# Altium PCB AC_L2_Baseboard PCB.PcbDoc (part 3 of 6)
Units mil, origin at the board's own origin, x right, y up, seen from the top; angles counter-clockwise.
Board outline 7290 x 7055 mil, 4 copper layers (Top Layer, Layer 1, Layer 2, Bottom Layer), stack 70.356 mil thick; 510 components, 285 nets, 1364 pads, 522 vias.
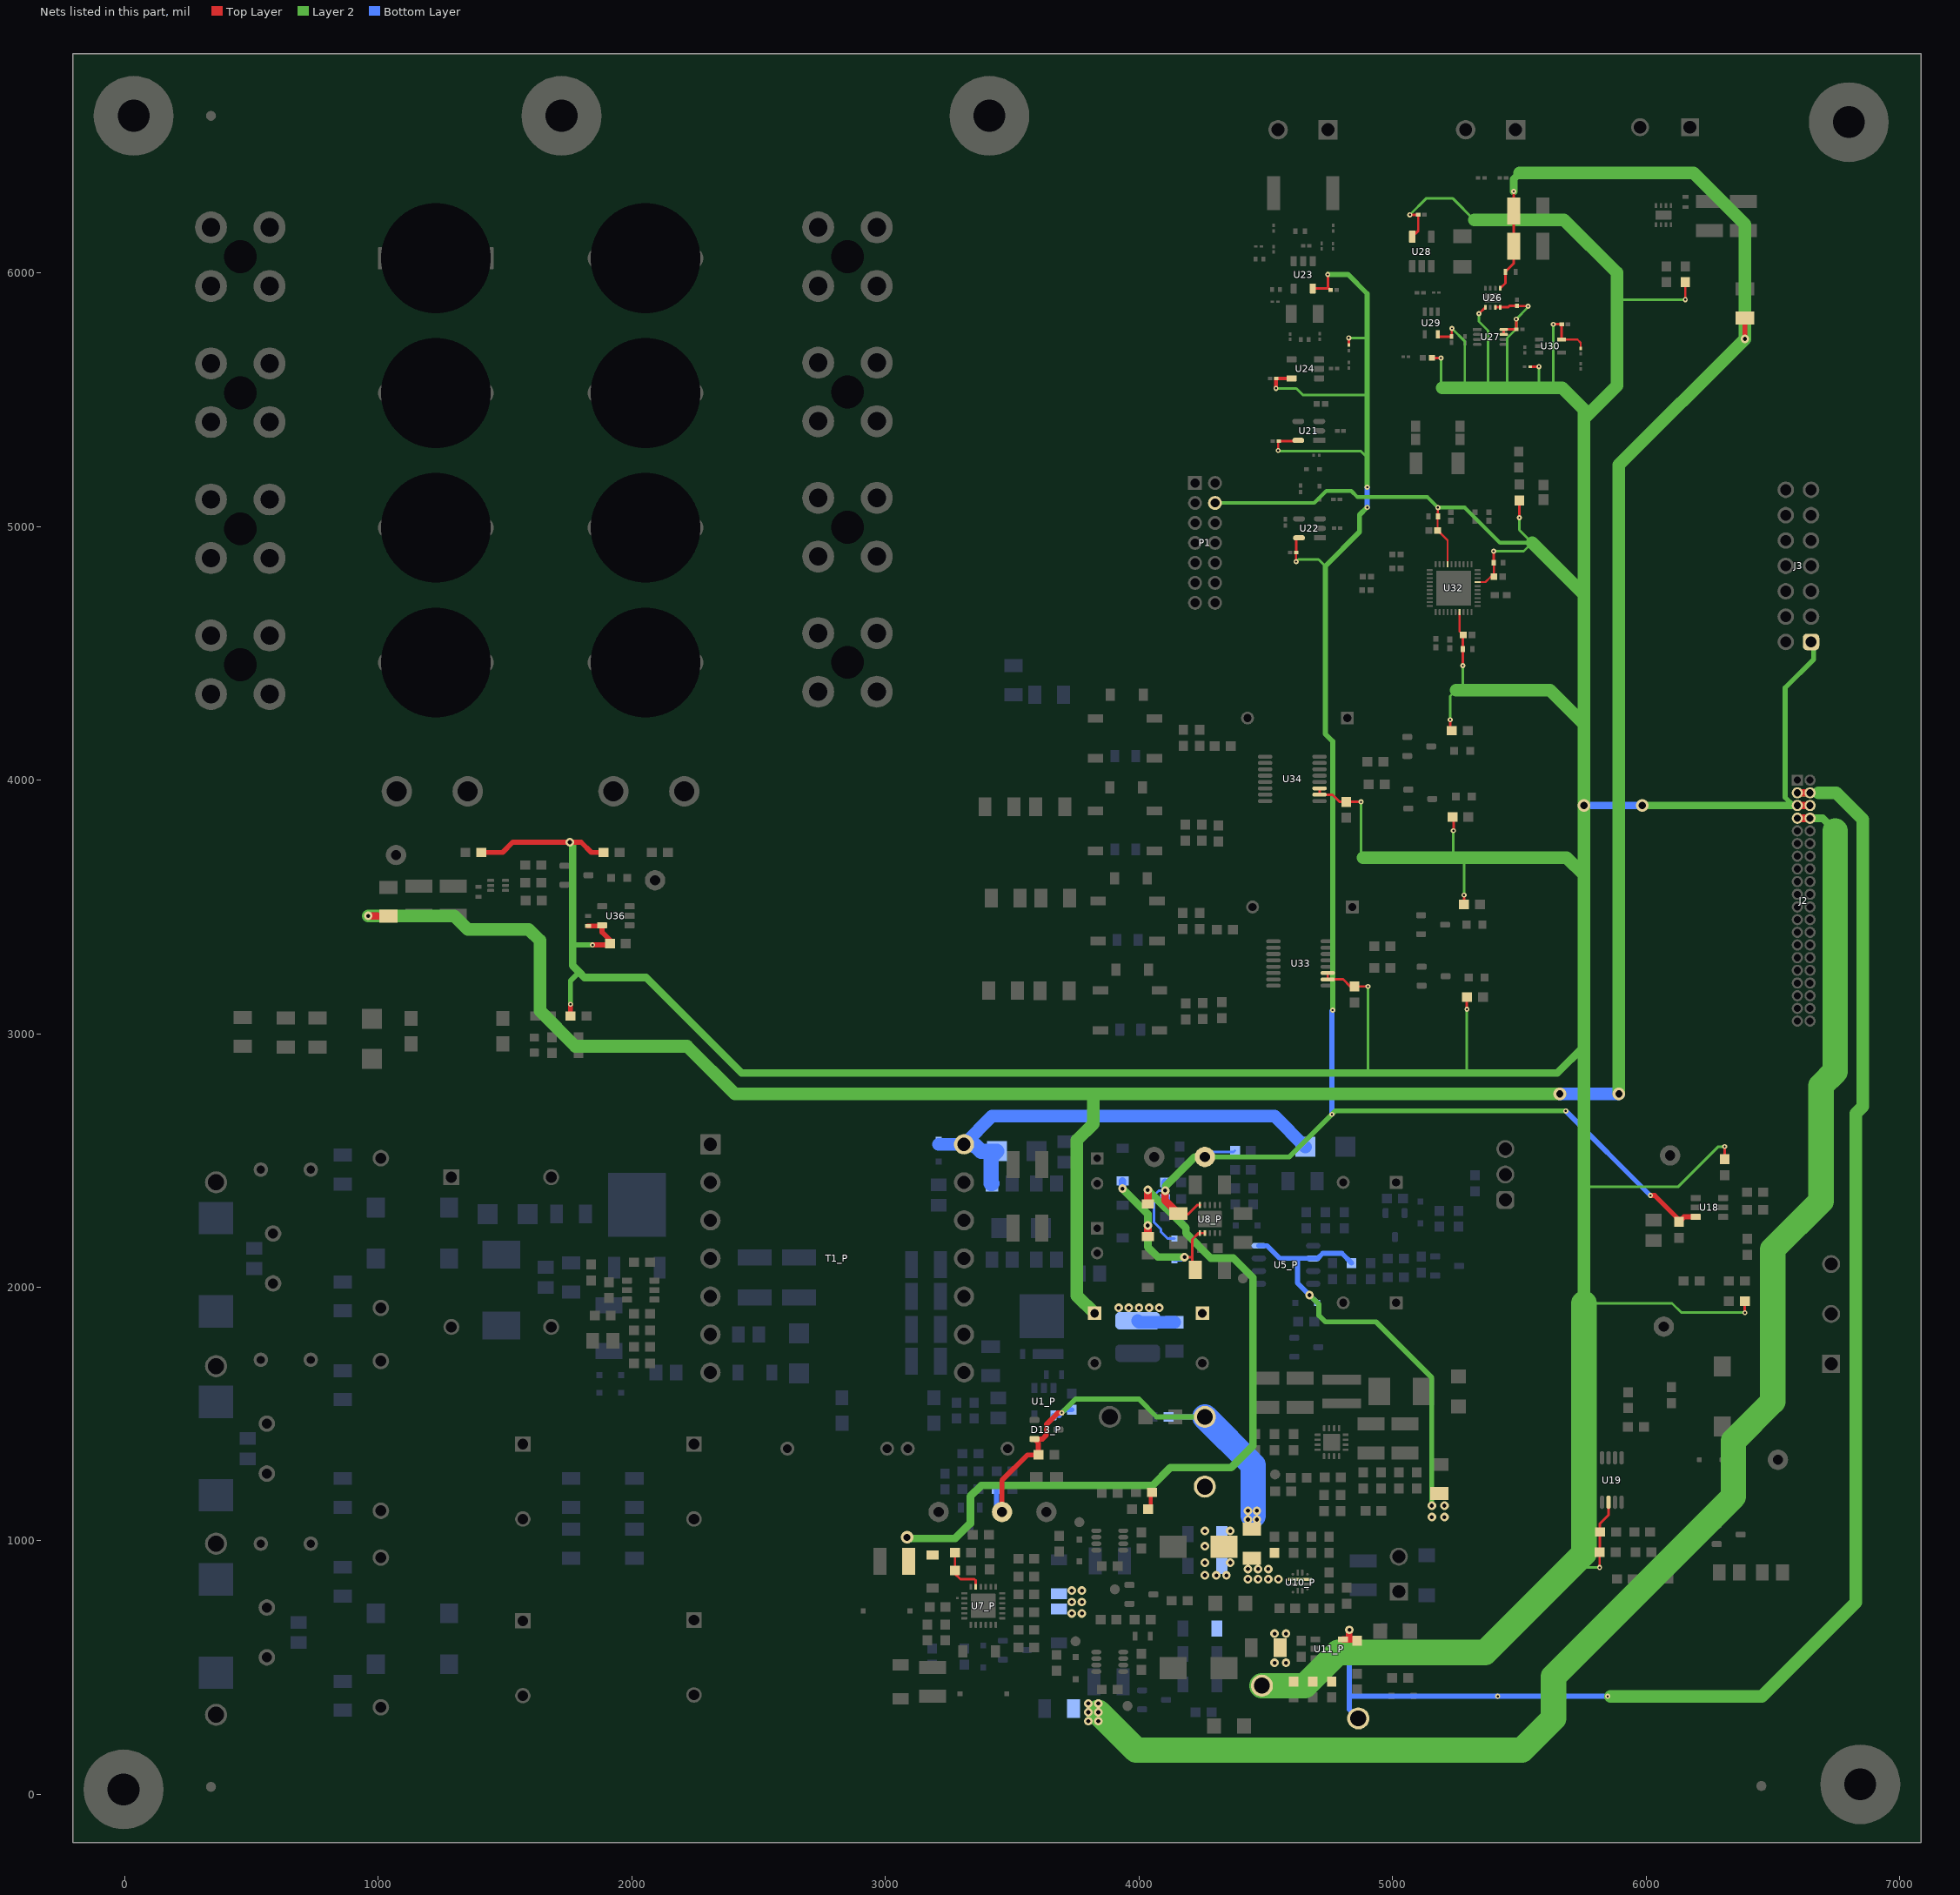
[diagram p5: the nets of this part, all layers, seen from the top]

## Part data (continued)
J16 J17: library part CMP-1502-03324-1, "Series 1377 - 5.00 mm Horizontal Entry with Pressure Clamp WR-TBL, 2 pin", Manufacturer="Wurth Elektronik", Operating Temperature=-30to120degC
J19 J20 J21 J22 J23 J24 J25 J26: library part CMP-0078526-1, "Power Element Bush, M3, TH", Current_A=50A, Manufacturer="Wurth Elektronik", Supplier Part Number 1=732-10882-1-ND
K1: library part CMP-0094655-1, "Power Her 40A 4NO 1NC 12VDC", Coil Current_A=333mA, Coil Power_W=490mW, Coil Resistance=36O, Coil Voltage_VDC=12V, Contact Rating_A=40A, Manufacturer=Panasonic, Operating Temperature Range=to, Switching Power=30W
L1_P L3_P: library part CMP-0003090-1, "Ferrite Bead, 1000 ohm @ 100 MHz, 0.2 A, 0805", Manufacturer="Wurth Elektronik", Supplier Part Number 1=732-1606-1-ND, Value1="0.45 ohm", Value2=0.2A, ValueDisplayed="1000 ohm"
L2_P L4_P L6_P: library part CMP-0064523-2, "Inductor, Wirewound, Ferrite, 150 uH, 2 A, 0.16 ohm, TH", Manufacturer="Wurth Elektronik", Value1="0.16 ohm", Value2=2A, ValueDisplayed=150uH
L5_P: library part CMP-0013107-2, "Coupled inductor, 6.8 mH, 1 A, 0.3 ohm, TH", Manufacturer="Wurth Elektronik", ValueDisplayed=6.8mH
L7_P: library part CMP-0064228-1
L8_P L10_P: library part CMP-0063804-1, "Inductor, Shielded Drum Core, Ferrite, 10 uH, 1 A, 0.12 ohm, SMD", Manufacturer="Wurth Elektronik", Supplier Part Number 1=732-1025-1-ND, Value1="0.12 ohm", Value2=1A, ValueDisplayed=10uH
L9_P L12_P L14_P: library part CMP-0003140-1, "Ferrite Bead, 280 ohm @ 100 MHz, 3.5 A, 1206", Manufacturer="Wurth Elektronik", Supplier Part Number 1=732-6132-1-ND, Value1="0.022 ohm", Value2=3.5A, ValueDisplayed="280 ohm"
L11_P L16_P: library part CMP-0086103-1, "Ferrite Bead, 600 ohm @ 100 MHz, 2.5 A, 1206", Manufacturer=Wuerth, Value1="0.038 ohm", Value2=2.5A, ValueDisplayed="600 ohm"
L13_P L17_P: library part CMP-0063928-1, "Inductor, Shielded Drum Core, Superflux, 4.7 uH, 6 A, 0.02 ohm, SMD", Manufacturer="Wurth Elektronik", Supplier Part Number 1=732-1153-1-ND, Value1="0.02 ohm", Value2=6A, ValueDisplayed=4.7uH
L15_P: library part CMP-0061090-1, "Inductor, Shielded, 3.3 uH, 5 A, 0.0286 ohm, SMD", Manufacturer=Coilcraft, Value1="0.0286 ohm", Value2=5A, ValueDisplayed=3.3uH
L18: library part CMP-0064815-2, "Inductor, Shielded Drum Core, Metal Composite, 220 uH, 0.44 A, 0.92 ohm, SMD", Manufacturer="Wurth Elektronik", Supplier Part Number 1=732-4045-1-ND, Value1="0.92 ohm", Value2=0.44A, ValueDisplayed=220uH
LBL1: library part CMP-0003625-1, "Thermal Transfer Printable Labels, 0.650\" W x 0.200\" H - 10,000 per roll", Manufacturer=Brady, Supplier Part Number 1=97C5133
LOGO1 LOGO5: library part CMP-0074835-1, "IEC 61010-1 High Voltage Warning"
Logo2: library part CMP-0074844-1
Logo3: library part CMP-0074847-1, "FCC_disclaimer"
Logo4: library part CMP-0074769-1
NT1_P NT2_P NT3: library part CMP-0078142-2, "Single point connection between nets.", Manufacturer=N/A
P1: library part CMP-2000-05240-1, "Header, Pitch 2 mm, 2 x 7 Position, Height 6.4 mm, Tail Length 2.5 mm, -55 to 105 degC, RoHS, Tube", Current Rating=2A, Manufacturer=Molex, Voltage Rating=125V
Q1_P: library part CMP-0089849-1, "Mosfet, N-Ch, 200V, 24A, 150Deg C Rohs Compliant: Yes", Digikey Part Number=BSC500N20NS3GATMA1CT-ND, Drain To Source Breakdown Voltage=200V, Input Capacitace At Vds="2770pF @ 100V", Manufacturer=Infineon, Operating Temperature Range="-55°C to +175°C", Pulse Drain Current=97A, Typ Forward Diode Voltage=1V
Q2_P: library part CMP-0091039-1, "Trans MOSFET N-CH 600V 4A 3-Pin(2+Tab) DPAK T/R", Digikey Part Number=IPD95R2K0P7ATMA1CT-ND, Drain To Source Breakdown Voltage=950V, Input Capacitace At Vds="330pF @ 400V", Manufacturer="Infineon Technologies", Mouser Part Number=726-IPD95R2K0P7ATMA1, Operating Temperature Range="-55°C to +150°C", Power_W=37W, Pulse Drain Current=10A, Typ Forward Diode Voltage=0.9V
Q3_P: library part CMP-0001232-1, "MOSFET, N-CH, 60 V, 14 A, TO-220FP", Alternate Manufacturer=None, Manufacturer=Vishay, Value2="24 nC"
Q4_P: library part CMP-0000419-2, "Transistor, NPN, 40 V, 0.2 A, SOT-23", Manufacturer="ON Semiconductor", Supplier Part Number 1=MMBT3904LT1GOSCT-ND, Value1="0.2 A", Value2=300
Q5_P Q6_P Q7_P Q8_P Q9: library part CMP-0000755-1, "MOSFET, N-CH, 50 V, 0.22 A, SOT-23", Alternate Manufacturer=None, Manufacturer="Fairchild Semiconductor", Supplier Part Number 1=BSS138CT-ND, Value2="1.7 nC"
Q10 Q11 Q12 Q13 Q14: library part CMP-0000377-2, "Transistor, NPN, 30 V, 0.1 A, SOT-23", Manufacturer="ON Semiconductor", Supplier Part Number 1=BC848CLT1GOSCT-ND, Value1="0.1 A", Value2=800
R1_P R6_P: library part CMP-0020619-3, "RES, 1.0 k, 5%, 0.125 W, AEC-Q200 Grade 0, 0805", Manufacturer=Panasonic, Power_W=125mW, Supplier Part Number 1=P1.0KACT-ND, TempCo="200 ppm/C", Tolerance_%=5%, Value2=0.125W, Value_Code=1k00, ValueDisplayed=1.0k
R2_P R4_P R7_P R9_P R12_P R16_P R19_P: library part CMP-0018684-3, "RES, 470 k, 5%, 0.25 W, AEC-Q200 Grade 0, 1206", Manufacturer=Vishay-Dale, Power_W=250mW, Supplier Part Number 1=541-470KECT-ND, TempCo="200 ppm/C", Tolerance_%=5%, Value2=0.25W, Value_Code=470k
R3_P R10_P R15_P: library part CMP-0020842-3, "RES, 10.0 k, 1%, 0.125 W, AEC-Q200 Grade 0, 0805", Manufacturer=Vishay-Dale, Power_W=125mW, Supplier Part Number 1=541-10.0KCCT-ND, TempCo="100 ppm/C", Tolerance_%=1%, Value2=0.125W, Value_Code=10k0, ValueDisplayed=10.0k
R5_P R8_P R13_P R17_P: library part CMP-0018610-3, "RES, 1.0 M, 5%, 0.25 W, AEC-Q200 Grade 0, 1206", Manufacturer=Vishay-Dale, Power_W=250mW, Supplier Part Number 1=541-1.0MECT-ND, TempCo="200 ppm/C", Tolerance_%=5%, Value2=0.25W, Value_Code=1M00, ValueDisplayed=1.0M
R11_P: library part CMP-0018578-3, "RES, 10, 5%, 0.25 W, AEC-Q200 Grade 0, 1206", Manufacturer=Vishay-Dale, Power_W=250mW, Supplier Part Number 1=541-10ECT-ND, TempCo="200 ppm/C", Tolerance_%=5%, Value2=0.25W, Value_Code=10R0, ValueDisplayed=10
R14_P R200_P: library part CMP-0018759-2, "RES, 0, 5%, 0.25 W, 1206", Manufacturer="Yageo America", Power_W=250mW, Supplier Part Number 1=311-0.0ERCT-ND, TempCo="200 ppm/C", Tolerance_%=5%, Value2=0.25W, Value_Code=0000, ValueDisplayed=0
R20_P R36_P R40_P R45_P R58_P R64_P R68_P R79_P: library part CMP-0023153-5, "RES, 4.70 k, 1%, 0.1 W, 0603", Manufacturer=Yageo, Power_W=100mW, Supplier Part Number 1=311-4.70KHRCT-ND, TempCo="100 ppm/C", Tolerance_%=1%, Value2=0.1W, Value_Code=4k70, ValueDisplayed=4.70k
R21_P: library part CMP-0022448-4, "RES, 49.9, 1%, 0.1 W, AEC-Q200 Grade 0, 0603", Manufacturer=Vishay-Dale, Power_W=100mW, Supplier Part Number 1=541-49.9HCT-ND, TempCo="100 ppm/C", Tolerance_%=1%, Value2=0.1W, Value_Code=49R9, ValueDisplayed=49.9
R22_P: library part CMP-0018603-3, "RES, 1.0 k, 5%, 0.25 W, AEC-Q200 Grade 0, 1206", Manufacturer=Vishay-Dale, Power_W=250mW, Supplier Part Number 1=541-1.0KECT-ND, TempCo="200 ppm/C", Tolerance_%=5%, Value2=0.25W, Value_Code=1k00, ValueDisplayed=1.0k
R23_P: library part CMP-0020497-3, "RES, 20, 5%, 0.125 W, AEC-Q200 Grade 0, 0805", Manufacturer=Vishay-Dale, Power_W=125mW, Supplier Part Number 1=541-20ACT-ND, TempCo="200 ppm/C", Tolerance_%=5%, Value2=0.125W, Value_Code=20R0, ValueDisplayed=20
R24_P: library part CMP-0022277-4, "RES, 2.49 k, 1%, 0.1 W, AEC-Q200 Grade 0, 0603", Manufacturer=Vishay-Dale, Power_W=100mW, Supplier Part Number 1=541-2.49KHCT-ND, TempCo="100 ppm/C", Tolerance_%=1%, Value2=0.1W, Value_Code=2k49, ValueDisplayed=2.49k
R25_P: library part CMP-0023252-5, "RES, 6.81 k, 1%, 0.1 W, 0603", Manufacturer=Yageo, Power_W=100mW, Supplier Part Number 1=311-6.81KHRCT-ND, TempCo="100 ppm/C", Tolerance_%=1%, Value2=0.1W, Value_Code=6k81, ValueDisplayed=6.81k
R26_P R28_P: library part CMP-0021759-3, "RES, 60.4 k, 1%, 0.125 W, AEC-Q200 Grade 0, 0805", Manufacturer=Panasonic, Power_W=125mW, Supplier Part Number 1=P60.4KCCT-ND, TempCo="100 ppm/C", Tolerance_%=1%, Value2=0.125W, Value_Code=60k4, ValueDisplayed=60.4k
R27_P: library part CMP-0023066-5, "RES, 38.3 k, 1%, 0.1 W, 0603", Manufacturer=Yageo, Power_W=100mW, Supplier Part Number 1=311-38.3KHRCT-ND, TempCo="100 ppm/C", Tolerance_%=1%, Value2=0.1W, Value_Code=38k3, ValueDisplayed=38.3k
R29 R83: library part CMP-0018664-3, "RES, 390 k, 5%, 0.25 W, AEC-Q200 Grade 0, 1206", Manufacturer=Vishay-Dale, Power_W=250mW, Supplier Part Number 1=541-390KECT-ND, TempCo="200 ppm/C", Tolerance_%=5%, Value2=0.25W, Value_Code=390k
R29_P R32_P R34_P R39_P R41_P R49_P R53_P R55_P R65_P R70_P R77_P R80_P: library part CMP-0022746-5, "RES, 10.0 k, 1%, 0.1 W, 0603", Manufacturer=Yageo, Power_W=100mW, Supplier Part Number 1=311-10.0KHRCT-ND, TempCo="100 ppm/C", Tolerance_%=1%, Value2=0.1W, Value_Code=10k0, ValueDisplayed=10.0k
R30_P R54_P R57_P R61_P R74_P: library part CMP-0021990-4, "RES, 100 k, 1%, 0.1 W, AEC-Q200 Grade 0, 0603", Manufacturer=Vishay-Dale, Power_W=100mW, Supplier Part Number 1=541-100KHCT-ND, TempCo="100 ppm/C", Tolerance_%=1%, Value2=0.1W, Value_Code=100k
R31_P R62_P: library part CMP-0023036-5, "RES, 33.2 k, 1%, 0.1 W, 0603", Manufacturer=Yageo, Power_W=100mW, Supplier Part Number 1=311-33.2KHRCT-ND, TempCo="100 ppm/C", Tolerance_%=1%, Value2=0.1W, Value_Code=33k2, ValueDisplayed=33.2k
R33_P R43_P R44_P: library part CMP-0022109-5, "RES, 1.00 k, 1%, 0.1 W, AEC-Q200 Grade 0, 0603", Manufacturer=Vishay-Dale, Power_W=100mW, Supplier Part Number 1=541-1.00KHCT-ND, TempCo="100 ppm/C", Tolerance_%=1%, Value2=0.1W, Value_Code=1k00, ValueDisplayed=1.00k
R35_P: library part CMP-0016530-2, "RES, 0.5, 1%, 1 W, 2010", Manufacturer="Stackpole Electronics Inc", Power_W=1W, Supplier Part Number 1=CSRN2010FKR500CT-ND, TempCo="250 ppm/C", Tolerance_%=1%, Value_Code=R500, ValueDisplayed=0.5
R37_P: library part CMP-0023037-5, "RES, 33.0 k, 1%, 0.1 W, 0603", Manufacturer=Yageo, Power_W=100mW, Supplier Part Number 1=311-33.0KHRCT-ND, TempCo="100 ppm/C", Tolerance_%=1%, Value2=0.1W, Value_Code=33k0, ValueDisplayed=33.0k
R38_P: library part CMP-0022478-4, "RES, 4.99, 1%, 0.1 W, AEC-Q200 Grade 0, 0603", Manufacturer=Vishay-Dale, Power_W=100mW, Supplier Part Number 1=541-4.99HHCT-ND, TempCo="100 ppm/C", Tolerance_%=1%, Value2=0.1W, Value_Code=4R99, ValueDisplayed=4.99
R42_P: library part CMP-0022762-5, "RES, 11.8 k, 1%, 0.1 W, 0603", Manufacturer=Yageo, Power_W=100mW, Supplier Part Number 1=311-11.8KHRCT-ND, TempCo="100 ppm/C", Tolerance_%=1%, Value2=0.1W, Value_Code=11k8, ValueDisplayed=11.8k
R46_P: library part CMP-0023318-5, "RES, 91.0 k, 1%, 0.1 W, 0603", Manufacturer=Yageo, Power_W=100mW, Supplier Part Number 1=311-91.0KHRCT-ND, TempCo="100 ppm/C", Tolerance_%=1%, Value2=0.1W, Value_Code=91k0, ValueDisplayed=91.0k
R47_P: library part CMP-0022661-3, "RES, 976 k, 1%, 0.1 W, AEC-Q200 Grade 0, 0603", Manufacturer=Vishay-Dale, Power_W=100mW, Supplier Part Number 1=541-976KHCT-ND, TempCo="100 ppm/C", Tolerance_%=1%, Value2=0.1W, Value_Code=976k
R48_P: library part CMP-0022655-4, "RES, 93.1 k, 1%, 0.1 W, AEC-Q200 Grade 0, 0603", Manufacturer=Vishay-Dale, Power_W=100mW, Supplier Part Number 1=541-93.1KHCT-ND, TempCo="100 ppm/C", Tolerance_%=1%, Value2=0.1W, Value_Code=93k1, ValueDisplayed=93.1k
R50_P: library part CMP-0023239-5, "RES, 68.0 k, 1%, 0.1 W, 0603", Manufacturer=Yageo, Power_W=100mW, Supplier Part Number 1=311-68.0KHRCT-ND, TempCo="100 ppm/C", Tolerance_%=1%, Value2=0.1W, Value_Code=68k0, ValueDisplayed=68.0k
R51_P: library part CMP-0023273-4, "RES, 787 k, 1%, 0.1 W, 0603", Manufacturer=Yageo, Power_W=100mW, Supplier Part Number 1=311-787KHRCT-ND, TempCo="100 ppm/C", Tolerance_%=1%, Value2=0.1W, Value_Code=787k
R52_P R69_P: library part CMP-0021991-4, "RES, 100, 1%, 0.1 W, AEC-Q200 Grade 0, 0603", Manufacturer=Vishay-Dale, Power_W=100mW, Supplier Part Number 1=541-100HCT-ND, TempCo="100 ppm/C", Tolerance_%=1%, Value2=0.1W, Value_Code=100R, ValueDisplayed=100
R56_P: library part CMP-0020835-3, "RES, 100, 1%, 0.125 W, AEC-Q200 Grade 0, 0805", Manufacturer=Vishay-Dale, Power_W=125mW, Supplier Part Number 1=541-100CCT-ND, TempCo="100 ppm/C", Tolerance_%=1%, Value2=0.125W, Value_Code=100R, ValueDisplayed=100
R60_P: library part CMP-0022436-4, "RES, 475 k, 1%, 0.1 W, AEC-Q200 Grade 0, 0603", Manufacturer=Vishay-Dale, Power_W=100mW, Supplier Part Number 1=541-475KHCT-ND, TempCo="100 ppm/C", Tolerance_%=1%, Value2=0.1W, Value_Code=475k
R63_P: library part CMP-0023342-3, "RES, 11.0 k, 1%, 0.1 W, AEC-Q200 Grade 0, 0603", Manufacturer="Stackpole Electronics Inc", Power_W=100mW, Supplier Part Number 1=RMCF0603FT11K0CT-ND, TempCo="100 ppm/C", Tolerance_%=1%, Value2=0.1W, Value_Code=11k0, ValueDisplayed=11.0k
R66_P: library part CMP-0022588-5, "RES, 750, 1%, 0.1 W, AEC-Q200 Grade 0, 0603", Manufacturer=Vishay-Dale, Power_W=100mW, Supplier Part Number 1=541-750HCT-ND, TempCo="100 ppm/C", Tolerance_%=1%, Value2=0.1W, Value_Code=750R, ValueDisplayed=750
R67_P R75_P R191: library part CMP-0023133-5, "RES, 47.0 k, 1%, 0.1 W, 0603", Manufacturer=Yageo, Power_W=100mW, Supplier Part Number 1=311-47.0KHRCT-ND, TempCo="100 ppm/C", Tolerance_%=1%, Value2=0.1W, Value_Code=47k0, ValueDisplayed=47.0k
R71_P: library part CMP-0022735-5, "RES, 100 k, 1%, 0.1 W, 0603", Manufacturer=Yageo, Power_W=100mW, Supplier Part Number 1=311-100KHRCT-ND, TempCo="100 ppm/C", Tolerance_%=1%, Value2=0.1W, Value_Code=100k
R72_P: library part CMP-0023162-4, "RES, 510 k, 1%, 0.1 W, 0603", Manufacturer=Yageo, Power_W=100mW, Supplier Part Number 1=311-510KHRCT-ND, TempCo="100 ppm/C", Tolerance_%=1%, Value2=0.1W, Value_Code=510k
R76_P: library part CMP-0023180-5, "RES, 54.9 k, 1%, 0.1 W, 0603", Manufacturer=Yageo, Power_W=100mW, Supplier Part Number 1=311-54.9KHRCT-ND, TempCo="100 ppm/C", Tolerance_%=1%, Value2=0.1W, Value_Code=54k9, ValueDisplayed=54.9k
R78_P: library part CMP-0025309-3, "RES, 46.4 k, 0.5%, 0.1 W, 0603", Manufacturer="Yageo America", Power_W=100mW, TempCo="50 ppm/C", Tolerance_%=0.5%, Value2=0.1W, Value_Code=46k4, ValueDisplayed=46.4k
R82: library part CMP-0025700-2, "RES, 100, 5%, 0.1 W, 0603", Manufacturer=Vishay-Dale, Power_W=100mW, Supplier Part Number 1=541-100GCT-ND, TempCo="200 ppm/C", Tolerance_%=5%, Value2=0.1W, Value_Code=100R, ValueDisplayed=100
R84: library part CMP-0025917-5, "RES, 39 k, 5%, 0.1 W, 0603", Manufacturer=Yageo, Power_W=100mW, Supplier Part Number 1=311-39KGRCT-ND, TempCo="100 ppm/C", Tolerance_%=5%, Value2=0.1W, Value_Code=39k0, ValueDisplayed=39k
R85: library part CMP-0025756-4, "RES, 220, 5%, 0.1 W, AEC-Q200 Grade 0, 0603", Manufacturer=Vishay-Dale, Power_W=100mW, Supplier Part Number 1=541-220GCT-ND, TempCo="200 ppm/C", Tolerance_%=5%, Value2=0.1W, Value_Code=220R, ValueDisplayed=220
R86 R88 R89 R94 R96: library part CMP-0022901-4, "RES, 200 k, 1%, 0.1 W, 0603", Manufacturer=Yageo, Power_W=100mW, Supplier Part Number 1=311-200KHRCT-ND, TempCo="100 ppm/C", Tolerance_%=1%, Value2=0.1W, Value_Code=200k
R87: library part CMP-0025899-5, "RES, 1.0 k, 5%, 0.1 W, 0603", Manufacturer=Yageo, Power_W=100mW, Supplier Part Number 1=311-1.0KGRCT-ND, TempCo="100 ppm/C", Tolerance_%=5%, Value2=0.1W, Value_Code=1k00, ValueDisplayed=1.0k
R90: library part CMP-0025931-5, "RES, 56 k, 5%, 0.1 W, 0603", Manufacturer=Yageo, Power_W=100mW, Supplier Part Number 1=311-56KGRCT-ND, TempCo="100 ppm/C", Tolerance_%=5%, Value2=0.1W, Value_Code=56k0, ValueDisplayed=56k
R91: library part CMP-0023232-5, "RES, 66.5 k, 1%, 0.1 W, 0603", Manufacturer=Yageo, Power_W=100mW, Supplier Part Number 1=311-66.5KHRCT-ND, TempCo="100 ppm/C", Tolerance_%=1%, Value2=0.1W, Value_Code=66k5, ValueDisplayed=66.5k
R92 R95: library part CMP-0022895-5, "RES, 1.00 k, 1%, 0.1 W, 0603", Manufacturer=Yageo, Power_W=100mW, Supplier Part Number 1=311-1.00KHRCT-ND, TempCo="100 ppm/C", Tolerance_%=1%, Value2=0.1W, Value_Code=1k00, ValueDisplayed=1.00k
R93: library part CMP-0020904-3, "RES, 150, 1%, 0.125 W, AEC-Q200 Grade 0, 0805", Manufacturer=Vishay-Dale, Power_W=125mW, Supplier Part Number 1=541-150CCT-ND, TempCo="100 ppm/C", Tolerance_%=1%, Value2=0.125W, Value_Code=150R, ValueDisplayed=150
R97: library part CMP-0082535-1, "RES, 330, 1%, 0.125 W, 0805", Manufacturer=Vishay-Dale, Power_W=125mW, Supplier Part Number 1=541-4142-1-ND, TempCo="100 ppm/C", Tolerance_%=1%, Value2=0.125W, Value_Code=330R, ValueDisplayed=330
R99 R175 R178 R179 R180 R184 R187 R189 R190: library part CMP-2002-06970-1, "RC0402JR-100RL", Manufacturer=Yageo
R125 R206 R209: library part CMP-0081973-1, "RES, 0, 0%, 0.25 W, AEC-Q200 Grade 0, 0603", Manufacturer=Vishay-Dale, Power_W=250mW, Supplier Part Number 1=541-2779-1-ND, Tolerance_%=0%, Value2=0.25W, Value_Code=0
R126 R210 R218: library part CMP-0025886-5, "RES, 10 k, 5%, 0.1 W, 0603", Manufacturer=Yageo, Power_W=100mW, Supplier Part Number 1=311-10KGRCT-ND, TempCo="100 ppm/C", Tolerance_%=5%, Value2=0.1W, Value_Code=10k0, ValueDisplayed=10k
R127 R130 R131 R134 R157: library part CMP-2004-00003-1, "CRCW0201100KFNED", Manufacturer=Vishay
R129: library part CMP-2002-01478-2, "Automotive Metal Thin Film Chip Resistor, 0402, 56kO, 0.1%, 25ppm/°C, 0.0625W, 75V", Case/Package=0402, Case Code (Metric)=1005, Max Operating Temperature=155°C, Max Power Dissipation=63mW, Min Operating Temperature=-55°C, Package Quantity=1, Power Rating=30mW, Resistance=56kR, Resistor Type="Thin Film", Temperature Coefficient=25ppm/°C, Tolerance=0.1%, Voltage Rating=25V
R133: library part CMP-2004-00015-1, "CRCW020110K0FKED", Manufacturer="Vishay Dale"
R135 R139 R141 R145 R148: library part CMP-2004-03995-1, Manufacturer="TE Connectivity / AMP", Part Number=CPF0201D3K83E1
R136: library part CMP-2004-00232-1, "CRCW02011K30FNED", Manufacturer="Vishay Dale"
R137 R138 R147 R151 R152 R154: library part CMP-2004-00208-1, "CRCW02011K00FKED", Manufacturer="Vishay Dale"
R140 R142 R146: library part CMP-2004-00846-1, "CRCW0201750RFKED", Manufacturer="Vishay Dale"
R143: library part CMP-0016024-1, "RES, 1.0 k, 5%, 1 W, 2512", Manufacturer=Panasonic, Power_W=1W, Supplier Part Number 1=PT1.0KXCT-ND, TempCo="200 ppm/C", Tolerance_%=5%, Value_Code=1k00, ValueDisplayed=1.0k
R144: library part CMP-2002-01772-2, "RESISTOR 0402 JUMPER ZERO OHM", Case/Package=0402, Case Code (Metric)=1005, Max Operating Temperature=155°C, Min Operating Temperature=-55°C, Power Rating=62.5mW, Resistance=0R, Temperature Coefficient=200ppm/°C, Tolerance=1%, Voltage Rating=50V
R153: library part CMP-1014-00013-3, "RES Thick Film, 3O, 5%, 0.25W, 200ppm/°C, 1206", Case/Package=1206, Case Code (Metric)=3216, Max Operating Temperature=155°C, Max Power Dissipation=250mW, Min Operating Temperature=-55°C, Package Quantity=1, Resistance=3R, Temperature Coefficient=200ppm/°C, Tolerance=5%, Voltage Rating=200V
R155: library part CMP-2004-00650-1, "CRCW0201499KFNED", Manufacturer="Vishay Dale"
R156: library part CMP-2004-00269-1, "CRCW02011M00FKED", Manufacturer="Vishay Dale"
R188: library part CMP-05422-000100-1, "RES SMD 1K OHM 0.1% 1/10W 0603", Case/Package=0603, Case Code (Metric)=1608, Max Operating Temperature=155°C, Max Power Dissipation=100mW, Min Operating Temperature=-55°C, Package Quantity=5000, Resistance=1kR, Resistance Tolerance=0.1%, Resistor Type="Thin Film", Temperature Coefficient=10ppm/°C, Voltage Rating=75V, Voltage Rating (DC)=150V
R192 R193 R195 R196 R200 R201 R203 R204: library part CMP-0018654-3, "RES, 30 k, 5%, 0.25 W, AEC-Q200 Grade 0, 1206", Manufacturer=Vishay-Dale, Power_W=250mW, Supplier Part Number 1=541-30KECT-ND, TempCo="200 ppm/C", Tolerance_%=5%, Value2=0.25W, Value_Code=30k0, ValueDisplayed=30k
R194 R198 R202 R207: library part CMP-0025930-5, "RES, 560, 5%, 0.1 W, 0603", Manufacturer=Yageo, Power_W=100mW, Supplier Part Number 1=311-560GRCT-ND, TempCo="100 ppm/C", Tolerance_%=5%, Value2=0.1W, Value_Code=560R, ValueDisplayed=560
R197 R199 R205 R208: library part CMP-0025719-4, "RES, 15 k, 5%, 0.1 W, AEC-Q200 Grade 0, 0603", Manufacturer=Vishay-Dale, Power_W=100mW, Supplier Part Number 1=541-15KGCT-ND, TempCo="200 ppm/C", Tolerance_%=5%, Value2=0.1W, Value_Code=15k0, ValueDisplayed=15k
R201_P: library part CMP-0022996-5, "RES, 2.70 k, 1%, 0.1 W, 0603", Manufacturer=Yageo, Power_W=100mW, Supplier Part Number 1=311-2.70KHRCT-ND, TempCo="100 ppm/C", Tolerance_%=1%, Value2=0.1W, Value_Code=2k70, ValueDisplayed=2.70k
R202_P: library part CMP-0022716-3, "RES, 0.47, 1%, 0.1 W, AEC-Q200 Grade 0, 0603", Manufacturer=Panasonic, Power_W=100mW, Supplier Part Number 1=P.47AJCT-ND, TempCo="300 ppm/C", Tolerance_%=1%, Value2=0.1W, Value_Code=R470, ValueDisplayed=0.47
R211 R212 R213 R214 R215 R217: library part CMP-0023219-5, "RES, 620, 1%, 0.1 W, 0603", Manufacturer=Yageo, Power_W=100mW, Supplier Part Number 1=311-620HRCT-ND, TempCo="100 ppm/C", Tolerance_%=1%, Value2=0.1W, Value_Code=620R, ValueDisplayed=620
R216 R219 R220 R221 R222: library part CMP-0022691-3, "RES, 20.0 k, 1%, 0.1 W, AEC-Q200 Grade 0, 0603", Manufacturer=Panasonic, Power_W=100mW, Supplier Part Number 1=P20.0KHCT-ND, TempCo="100 ppm/C", Tolerance_%=1%, Value2=0.1W, Value_Code=20k0, ValueDisplayed=20.0k
R800 R801 R802 R803: library part CMP-0092692-1, "RES SMD 0 OHM JUMPER 1/8W 0805", Digikey Part Number=311-0.0CRCT-ND, Manufacturer=Yageo, Mouser Part Number=603-RC0805FR-070RL, Operating Temperature Range="-55°C to +155°C", Power_W=125mW, Tolerance_%=1%
RT1_P RT2_P RT3_P: library part CMP-0002556-2, "Thermistor NTC, 4.70 ohm, 20%, 8.5mm Disc", Manufacturer=TDK, Power_W=1.4W, Supplier Part Number 1=B57153S479M51-ND, Tolerance_%=20%
T1_P: library part CMP-0094994-1, "Tranformer, Flyback, 30W, THT", Frequency_Fixed=40kHz, Manufacturer=Wurth, Operating Temperature Range="-40°C to +125°C", Voltage_Isolation_Vrms=500V
TP1_P TP2_P TP3_P TP5_P: library part CMP-0055149-2, "Test Point, Multipurpose, White, TH", Color=White, Manufacturer="Keystone Electronics", Supplier Part Number 1=36-5012-ND
TP4_P TP14_P TP16_P TP19_P: library part CMP-0055147-2, "Test Point, Multipurpose, Red, TH", Color=Red, Manufacturer="Keystone Electronics", Supplier Part Number 1=36-5010-ND
TP6_P TP11_P: library part CMP-0055137-2, "Test Point, Miniature, Red, TH", Color=Red, Manufacturer="Keystone Electronics", Supplier Part Number 1=36-5000-ND
TP7_P: library part CMP-0055148-2, "Test Point, Multipurpose, Black, TH", Color=Black, Manufacturer="Keystone Electronics", Supplier Part Number 1=36-5011-ND
TP8_P: library part CMP-0055140-2, "Test Point, Miniature, Orange, TH", Color=Orange, Manufacturer="Keystone Electronics", Supplier Part Number 1=36-5003-ND
TP9_P TP12_P: library part CMP-0055138-2, "Test Point, Miniature, Black, TH", Color=Black, Manufacturer="Keystone Electronics", Supplier Part Number 1=36-5001-ND
TP10_P TP13_P TP15_P TP17_P TP18_P TP20_P: library part CMP-0003825-1, "1mm Test Point, SMT", Manufacturer=Any
TP24 TP25 TP26 TP27 TP28: library part CMP-0055140-1, "Test Point, Miniature, Orange, TH", Color=Orange, Manufacturer=Keystone, Supplier Part Number 1=36-5003-ND
U1_P: library part CMP-0013050-3, "High-Frequency Multi-Mode Synchronous Rectifier Controller, DBV0005A (SOT-23-5)", Alternate Manufacturer="Texas Instruments", Alternate PartNumber=UCC24612-1DBVT
U2_P: library part CMP-0006177-3, "Optocoupler, 5 kV, 80-160% CTR, SMT", Manufacturer="Fairchild Semiconductor", Supplier Part Number 1=FOD817A3SDCT-ND, Voltage_Isolation_Vrms=5kV
U3_P: library part CMP-0078369-2, "High-Efficiency Low-Cost Flyback Controller with Secondary-Side Regulation, DBV0006A (SOT-23-6)", Alternate Manufacturer="Texas Instruments"
U4_P: library part CMP-0033091-1, "Adjustable Precision Shunt Regulator, 34 ppm / degC, 100 mA, -40 to 85 degC, 3-pin SOT-23 (DBZ), Green (RoHS & no Sb/Br)", Manufacturer="Texas Instruments", Rating=Catalog, Temp Coeff(Max)(ppm/ degree C)=92, Temp Coeff(Typ)(ppm/ degree C)=34
U5_P: library part CMP-0032057-1, "Single Supply Voltage Supervisor for 5 V Systems with Programmable Time Delay, 1 Supply Monitored, -40 to 85 degC, 8-pin SOIC (D), Green (RoHS & no Sb/Br)", Manufacturer="Texas Instruments", Rating=Catalog, Threshold Voltage 1 (typ)(Typ)(V)=4.55
U6_P: library part CMP-0066199-1, "2.5V Low Iq Adjustable Precision Shunt Regulator, DBZ0003A (SOT-23-3)", Alternate Manufacturer="Texas Instruments"
U7_P: library part CMP-0034952-2, "Postive and Negative Output DC-DC Converter, 2.7 to 5.5 V, -40 to 85 degC, 24-pin QFN (RGE24), Green (RoHS & no Sb/Br)", Manufacturer="Texas Instruments", Rating=Catalog, Switching Frequency(Typ)(kHz)=1400
U8_P: library part CMP-0013435-7, "Dual, 150mA, Wide-Vin, Positive and Negative Low-Dropout (LDO) Voltage Regulator, DSC0010J (WSON-10)", Alternate Manufacturer="Texas Instruments", Alternate PartNumber=TPS7A3901DSCT, Operating Temperature Range="-40 to 125 C", Rating=Catalog
U9_P U13_P: library part CMP-0013290-3, "17V Input, 3A Synchronous Step-Down Regulator in SOT-23 w/ Advanced Eco-mode™, PG, Soft Start, DDF0008A (SOT-23-THN-8)", Alternate Manufacturer="Texas Instruments", Alternate PartNumber=TPS563210ADDFT, Operating Temperature Range="-40 to 85 C", Rating=Catalog
U10_P: library part CMP-0091660-1, "2.7 - 23 V, 5.5 A, 28 mO True Reverse Current Blocking eFuse with Input Reverse Polarity Protection", Manufacturer="Texas Instruments", Max Supply Voltage=23V, Min Supply Voltage=2.7V, Nominal Supply Current=428uA, Operating Temperature Range="-40°C to +125°C", Output Voltage=2.7-23V
U11_P: library part CMP-0035639-1, "Single Output LDO, 150 mA, Fixed 1.8 V Output, 2.7 to 10 V Input, with Low IQ, 5-pin SOT-23 (DBV), -40 to 125 degC, Green (RoHS & no Sb/Br)", Manufacturer="Texas Instruments"
U12_P: library part CMP-0067160-2, "Integrated 5-A 24-V Wide Input Range Boost/SEPIC/Flyback DC-DC Regulator, RTE0016C (WQFN-16)", Alternate Manufacturer="Texas Instruments", Alternate PartNumber=TPS55330RTET
U14: library part CMP-0006177-3, "Optocoupler, 5 kV, 80-160% CTR, SMT", Manufacturer="Fairchild Semiconductor", Supplier Part Number 1=FOD817AS-ND, Voltage_Isolation_Vrms=5kV
U18: library part CMP-0080757-2, "40 V, microPower, Push-Pull Comparator with Shutdown, DBV0006A (SOT-23-6)", Alternate Manufacturer="Texas Instruments"
U19: library part CMP-0077684-1, "2 Channel, 200 ksps to 500 ksps  12-Bit A/D Converter, DGK0008A (VSSOP-8)", Alternate Manufacturer="Texas Instruments", Alternate PartNumber=ADC122S051QIMM/NOPB
U20: library part CMP-0090279-1, "1.6A H-bridge motor driver, PWM, PH/EN, ½ bridge control, with low power sleep mode", Manufacturer="Texas Instruments", Max Supply Voltage=18V, Min Supply Voltage=4.5V, Operating Temperature Range="-40°C to +150°C", Switching Frequency=100kHz
U21 U22: library part CMP-04895-000139-1, "IC OPAMP GP 1 CIRCUIT SOT23-5", Case/Package=SOT-23-5, Input Bias Current=10pA, Input Offset Voltage (Vos)=500uV, Max Operating Temperature=125°C, Min Operating Temperature=-40°C, Operating Supply Current=1.6mA, Output Current Per Channel=75mA
U23 U24: library part CMP-0860961-1, "14MHz, MUX-friendly, low-noise, zero-drift, RRO, CMOS precision operational amplifier, DBV0005A (SOT-23-5)", Alternate Manufacturer="Texas Instruments", Alternate PartNumber=OPA189IDBVT, Operating Temperature Range="-40 to 125 C", Rating=Catalog
U26: library part CMP-0089585-1, "Low-Voltage H-Bridge Driver", Manufacturer="Texas Instruments", Max Supply Voltage=18V, Min Supply Voltage=4.5V, Nominal Supply Current=600-3000uA, Operating Temperature Range="-40°C to +150°C", Switching Frequency=100kHz
U27: library part CMP-0859-00648-4, "IC FF D-TYPE SNGL 1BIT US8", Ambient Temperature Range High=+125°C, Ambient Temperature Range Low=-40°C, Frequency=140MHz, Manufacturer="Texas Instruments", Max Supply Voltage=5.5V, Min Supply Voltage=1.65V, Nominal Supply Current=10uA, Package=DCU0008A, Temperature="-40°C to +125°C"
U28: library part CMP-0750213-2, "INA293 High-Voltage, High Bandwidth, Unidirectional, 110-V Common-Mode, Current-Sense Amplifier, DBV0005A (SOT-23-5)", Alternate Manufacturer="Texas Instruments", Alternate PartNumber=INA293A1IDBVT
U29 U30: library part CMP-0860894-1, "Low power, small size comparator with push-pull output, DCK0005A (SOT-SC70-5)", Alternate Manufacturer="Texas Instruments", Alternate PartNumber=TLV7011DCKT, Operating Temperature Range="-40 to 125 C", Rating=Catalog
U32: library part CMP-0038830-4, "MSP430F51x2 Mixed Signal Microcontroller, RSB0040B (WQFN-40)", Frequency(MHz)=25, Manufacturer="Texas Instruments", Operating Temperature Range="-40 to 85 C", Rating=Catalog
U33 U34: library part CMP-0013034-2, "ISO1212DBQR, DBQ00016A, DBQ0016A (SSOP-16)", Alternate Manufacturer="Texas Instruments", Alternate PartNumber=ISO1212DBQ
U35: library part CMP-0090278-2, "18V, 1A H-bridge motor driver, PWM, PH/EN, ½ bridge control, with low power sleep mode", Manufacturer="Texas Instruments", Max Supply Voltage=18V, Min Supply Voltage=4.5V, Operating Temperature Range="-40°C to +150°C", Switching Frequency=100kHz
U36: library part CMP-0051576-2, "Low-Power Single 2-Input Positive-AND Gate, DBV0005A (SOT-23-5)", F @ Nom Voltage(Max)(Mhz)=100, Generic Part Number=SN74AUP1G08, ICC @ Nom Voltage(Max)(mA)=0.0009, Manufacturer="Texas Instruments", Operating Temperature Range="-40 to 85 C", Rating=Catalog, tpd @ Nom Voltage(Max)(ns)=32.8,20.9,14.2,11,7.6,6.2, Voltage(Nom)(V)=0.8,1.2,1.5,1.8,2.5,3.3
Y1: library part CMP-27762-013278-1, "CRYSTAL 32.7680KHZ 12.5PF SMD", Case/Package=CSMD, ESR (Equivalent Series Resistance)=70kR, Frequency=32.768kHz, Frequency Tolerance=10ppm, Load Capacitance=12.5pF, Max Operating Temperature=85°C, Min Operating Temperature=-40°C, Operating Frequency="32.768 kHz", Package Quantity=3000

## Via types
v1: diameter 34, hole 16, Top Layer to Bottom Layer, tented both sides, 231 vias
v2: diameter 20, hole 8, Top Layer to Bottom Layer, tented both sides, 209 vias
v3: diameter 50, hole 28, Top Layer to Bottom Layer, tented both sides, 48 vias
v4: diameter 19.68, hole 7.87, Top Layer to Bottom Layer, 29 vias
v5: diameter 24, hole 12, Top Layer to Bottom Layer, 5 vias

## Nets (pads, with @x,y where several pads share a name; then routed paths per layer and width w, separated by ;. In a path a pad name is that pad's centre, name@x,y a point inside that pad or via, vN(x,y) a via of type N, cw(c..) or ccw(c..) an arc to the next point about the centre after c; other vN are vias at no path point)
1V8: C78_P.1 J2.3 J2.4 TP16_P.1 U11_P.5 | length 6063.9
  Top Layer w20: v1(4830,649) v1@4833.5,645.5
  Top Layer w25: U11_P.5@4804.13,611.4 4829.11,611.4 ; v1(4830,649) 4829.11,648.11 4829.11,611.4 ; C78_P.1@4860,605.5 4854.09,611.4 4829.11,611.4
  Top Layer w30: J2.3@6597,3950 J2.4@6647,3950
  Layer 2 w20: v2(5849,387) 5860,387
  Layer 2 w30: J2.3@6600.99,3946.01 J2.3@6597,3950 6672.02,3950
  Layer 2 w50: 5860,387 6457,387 6827,757 6827,2685 6855,2713 6855,3845 6750,3950 6680,3950
  Bottom Layer w20: v1(4830,649) 4830,387.27 ; TP16_P.1@4865,300 4830,335 4830,387.27 ; v2(5849,387) v2(5415,387) 4830.27,387 4830,387.27
3V3: C68_P.1 C69_P.1 C70_P.1 C71_P.2 C108.1 C109.1 C125.2 C126.2 C127.2 C128.2 C149.1 C150.2 C152.1 C153.2 C154.1 C155.2 C157.1 C164.1 C167.1 C800.2 J2.5 J2.6 J3.1 L12_P.2 P1.4 R82.2 R86.2 R90.2 R126.1 R129.2 R130.2 R157.1 R191.2 R210.2 R211.2 R212.2 R213.2 R214.2 R215.2 R217.2 TP14_P.1 U19.2 U26.5 U26.7 U26.8 U27.7 U27.8 U28.5 U29.5 U30.5 U32.17 U32.27 U32.37 U33.2 U33.3 U34.2 U34.3 U36.5 | length 25613.5
  Top Layer w8: R82.2@1758,3070.5 R82.2@1758.5,3070 ; v2(5179.26,5074.96) C154.1@5179.26,5039.96 5177.88,5038.58 C155.2@5177.88,4984.96 5217.41,4945.43 U32.37@5217.41,4851.89 ; U32.17@5264.65,4662.91 5264.65,4586.46 C150.2@5278.71,4572.4 ; U32.27@5335.52,4781.02 5366.62,4781.02 5388,4802.4 C153.2@5400.08,4802.4 ; U30.5@5666.85,5737.55 5729.45,5737.55 5742.56,5724.44 R130.2@5742.56,5702.79
  Top Layer w10: R210.2@1910.57,3355 R210.2@1913.5,3355 ; U34.3@4712.28,3967.81 U34.2@4712.28,3942.81 4762.64,3942.81 4790.94,3914.51 C164.1@4817.44,3914.51 v2(4875.94,3914.51) ; U33.3@4744.84,3239.37 U33.2@4744.84,3214.37 4805.63,3214.37 4833.5,3186.5 C157.1@4850,3186.5 v2(4903.5,3186.5) ; v2(5068.49,6229.57) 5068.68,6229.77 5101.4,6229.77 C127.2@5101.6,6229.96 5101.6,6166.47 U28.5@5078.16,6143.03 ; R129.2@5155.81,5665.26 5156.18,5664.89 5190.95,5664.89 v2(5191.32,5664.51) ; U29.5@5178.15,5758.56 5178.15,5752.3 5181.02,5749.42 C125.2@5232.96,5749.42 5233.69,5750.16 5233.69,5780.63 v2(5234.42,5781.37) ; v2(5227.44,4238.01) 5227.44,4209.25 5237.44,4199.25 R215.2@5233.5,4195.31 ; v2@5241.5,3801 5241.5,3835.31 ; v2(5277.33,4451.73) C149.1@5277.33,4517.4 5277.33,4571.02 C150.2@5278.71,4572.4 ; R213.2@5282.01,3510 v2(5282.01,3547.01) ; v2(5293.5,3096.5) R212.2@5293.5,3145 ; v2(5341.19,5839.96) U26.5@5366.19,5864.96 ; v2(5398.71,4903.11) C152.1@5398.71,4857.4 5400.08,4856.02 C153.2@5400.08,4802.4 ; U26.7@5405.56,5864.96 U26.8@5425.24,5864.96 5455.96,5864.96 5461.58,5870.58 C126.2@5491.04,5870.58 5491.83,5869.79 5534.21,5869.79 v2(5535,5869) ; U27.7@5438.76,5757.8 U27.8@5438.76,5777.49 5439.01,5777.74 5487.76,5777.74 C800.2@5488.02,5778 5488.06,5778.04 5488.06,5818.22 v2(5488.11,5818.27) ; v2(5500.56,5034.96) R191.2@5500.56,5103.46 ; R157.1@5543.38,5630.96 v2(5577.56,5630.96) ; v2(5634.43,5797.96) C128.2@5667.58,5797.96 5667.75,5797.96 5667.21,5797.43 5667.21,5737.91 U30.5@5666.85,5737.55 ; v2@5817.01,892.01 v2(5817.01,895) C108.1@5817.01,955 5818.5,956.5 C109.1@5818.5,1035 5818.5,1068.5 5852.2,1102.2 U19.2@5852.2,1152.4 ; 6155,5905 R126.1@6155,5963.5 ; R86.2@6310,2505 v2(6310,2555) ; v2(6389.84,1900) R90.2@6389.84,1945
  Top Layer w20: R217.2@1406.5,3715 1490,3715 1530,3755 v1(1755,3755) 1800,3755 1839.96,3715.04 R211.2@1888.48,3715.04 ; R82.2@1758,3070.5 v2(1758,3116) ; C167.1@1826.47,3425.04 1879.74,3425.04 U36.5@1882.34,3427.64 1882.34,3400.66 1913.5,3369.5 R210.2@1913.5,3355 ; v2(1845,3350) 1905.57,3350 R210.2@1910.57,3355
  Top Layer w30: J2.5@6597,3900 J2.6@6647,3900
  Layer 2 w10: 1766,3355 1771,3350 ; v2(4875.94,3914.51) 4875.94,3703.06 4884,3695 ; 4902,2845 4903.5,2846.5 v2(4903.5,3186.5) ; v2(5068.49,6229.57) 5134,6295.08 5236.92,6295.08 5323,6209 ; v2(5191.32,5664.51) 5191.32,5551.68 5196,5547 ; v2(5227.44,4238.01) 5227.44,4331.44 5251,4355 ; v2(5234.42,5781.37) 5285,5730.79 5285,5549 5283,5547 ; v2(5240,3801) 5240,3699 5244,3695 ; v2(5277.33,4451.73) 5277.33,4359.67 5282,4355 ; v2(5282.01,3547.01) 5282.01,3690.01 5287,3695 ; 5289,2845 5293.5,2849.5 v2(5293.5,3096.5) ; v2(5341.19,5839.96) 5341.19,5808.81 5377,5773 5377,5547 ; v2(5398.71,4903.11) 5518.11,4903.11 5551,4936 5500.56,4986.44 v2(5500.56,5034.96) ; 5452,5547 5452,5744 5488.11,5780.11 v2(5488.11,5818.27) 5535,5865.16 v2(5535,5869) ; v2(5577.56,5630.96) 5577.56,5549.44 5580,5547 ; v2(5634.43,5797.96) 5634.43,5554.57 5642,5547 ; 5755,900 5760,895 v2(5817.01,895) ; 5755,1937 6103,1937 6140,1900 v2(6389.84,1900) ; 5755,2396 6126,2396 6285,2555 v2(6310,2555) ; 5885,5897 5887,5895 v2(6155,5895) ; J2.5@6581,3900 J2.5@6597,3900
  Layer 2 w15: P1.4@4300,5093.26 4691.26,5093.26 4739,5141 4837,5141 4862,5116 5138.22,5116 v2(5179.26,5074.96) 5285.04,5074.96 5424,4936 5551,4936
  Layer 2 w20: v2(1758,3116) 1758,3209 1792,3243 ; 1771,3350 v2(1845,3350) ; J2.5@6581,3900 6549,3932 6549,4364 6661,4476 J3.1@6661,4544
  Layer 2 w30: v1(1755,3755) 1766,3744 1766,3355 1766,3269 1792,3243 1813,3222 2056,3222 2433,2845 4902,2845 5289,2845 5650,2845 5755,2950 ; v3(5985,3900) J2.5@6581,3900
  Layer 2 w50: 4884,3695 5244,3695 5287,3695 5687,3695 5755,3627 ; 5196,5547 5283,5547 5377,5547 5452,5547 5580,5547 5642,5547 5669,5547 5755,5461 5755,5426 ; 5251,4355 5282,4355 5621,4355 5755,4221 ; 5323,6209 5677,6209 5885,6001 5885,5897 5885,5556 5755,5426 ; 5551,4936 5755,4732 ; 5755,1937 5755,2396 5755,2950 5755,3627 ; 5755,3627 v3(5755,3900) 5755,4221 ; 5755,4221 5755,4732 ; 5755,4732 5755,5426
  Layer 2 w100: TP14_P.1@4485,429 4654,429 4785,560 5365,560 5755,950 5755,1937
  Bottom Layer w30: v3(5755,3900) v3(5985,3900)
  other v1: 4535,519 4580,519 4535,634 4580,634
5V: C89_P.1 C90_P.1 J2.7 J2.8 L9_P.1 L17_P.2 R74_P.2 R76_P.2 TP19_P.1 | length 6157.9
  Top Layer w15: R74_P.2@4046.5,1124 4046.5,1186.4 R76_P.2@4051.5,1191.4
  Top Layer w30: J2.7@6597,3850 J2.8@6647,3850
  Layer 2 w30: J2.7@6597,3850 J2.8@6647,3850 6696,3850 6746,3800
  Layer 2 w100: v1(3840,324) 3989,175 5510,175 5635,300 5635,465 6345,1175 6345,1395 6500,1550 6500,2150 6690,2340 6690,2795 6746,2851 6746,3800
  other v1: 3800,289 3840,289 3800,324 3800,359 3840,359 4260,864.2 4305,864 4345,864 4260,914 4360,914 4260,979 4260,1039 4360,1039
12V_In: C18_P.1 C25_P.1 C26_P.1 C138.1 C139.1 C140.1 D13_P.2 F4.2 F5.2 L7_P.2 R14_P.1 R20_P.2 R21_P.2 R30_P.1 R200_P.2 TP4_P.1 TP6_P.1 U1_P.4 U26.1 | length 13676.4
  Top Layer w10: U26.1@5425.24,5939.76 5445.56,5960.08 C140.1@5445.56,6004.96 5478.47,6037.87 C138.1@5478.47,6104.96 C139.1@5478.47,6244.96 5478.47,6321.53 v2(5478,6322)
  Top Layer w20: TP6_P.1@3460,1114 3460,1239 3560,1339 R30_P.1@3603.5,1339 3603.5,1385.85 D13_P.2@3587.76,1401.6 3619.25,1401.6 3635,1417.35 3635,1458.69 3681.18,1504.87 v2(3695.87,1504.87) ; v1(6390,5740) F4.2@6390,5822.91
  Top Layer w30: v1(960,3465) F5.2@1040,3462.91
  Layer 2 w20: v2(3695.87,1504.87) 3750,1559 4000,1559 4070,1489 TP4_P.1@4260,1489
  Layer 2 w30: v2(5478,6322) 5478,6371 5502,6395
  Layer 2 w50: v1(960,3465) 1300,3465 1353,3412 1593,3412 1637.5,3367.5 1637.5,3090.5 1777.3,2950.7 2218.3,2950.7 2406,2763 3820,2763 ; C25_P.1@3825,1897.43 3755,1967.43 3755,2580 3820,2645 3820,2763 ; 5502,6395 6187.97,6395 6390,6192.97 v1(6390,5740) 5893,5243 v3(5893,2763) ; v3(5660,2763) 3820,2763
  Bottom Layer w20: R21_P.2@3438.5,1204 3438.5,1135.5 TP6_P.1@3460,1114 ; U1_P.4@3662.4,1494.87 3684.13,1494.87 3685,1494 v2(3695.87,1504.87) 3708.5,1517.5 C18_P.1@3735,1517.5 ; R20_P.2@4116.5,1489 TP4_P.1@4260,1489
  Bottom Layer w50: L7_P.2@3995,1867.98 4000.89,1862.09 R200_P.2@4140,1862.09 ; v3(5660,2763) v3(5893,2763)
  Bottom Layer w100: TP4_P.1@4260,1489 4450,1299 4450,1099
  other v1: 4430,1084 4465,1084 4430,1119 4465,1119 3920,1919 3960,1919 4000,1919 4040,1919 4080,1919
+12V: C40_P.1 C72_P.1 D18_P.1 L11_P.1 L14_P.2 L16_P.1 R14_P.2 U5_P.2 U5_P.8 U10_P.6 | length 1765.8
  Layer 2 w20: v1(4672.81,1969.5) 4710,1932.31 4710,1889 4735,1864 4935,1864 5155,1644 v1(5155,1139)
  Bottom Layer w20: U5_P.8@4472.72,2164 4505,2164 4555,2114 4625,2114 ; D18_P.1@4703.31,1939 v1(4672.81,1969.5) 4625,2017.31 4625,2114 ; C40_P.1@4838.7,2095.5 4800.2,2134 4725,2134 4705,2114 U5_P.2@4687.28,2114 4625,2114
  other v1: 3735,714 3775,714 3735,759 3775,759 3735,804 3775,804 4430,849 4470,849 4510,849 4550,849 4430,889 4470,889 4510,889 5155,1094 5205,1094 5205,1139
+12Va: C46_P.2 C47_P.1 C48_P.1 C99.1 C121.2 C122.2 C123.2 C124.2 D21_P.2 R46_P.1 R127.2 TP11_P.1 U8_P.10 U18.6 U21.5 U22.5 U23.5 U24.5 | length 8020
  Top Layer w8: v2(4620,4862) 4620,4897.44 C124.2@4620.54,4897.98
  Top Layer w10: C47_P.1@4157.09,2289 4195,2289 4230.12,2324.12 U8_P.10@4240.63,2324.12 ; v2(4549,5300) 4549,5334.84 C123.2@4551.57,5337.4 4625.63,5337.4 U21.5@4628.23,5340 ; C124.2@4620.54,4897.98 4620.37,4897.98 4620.37,4950.52 4625.43,4955.57 U22.5@4631.2,4955.57 ; U23.5@4685.4,5938.87 C121.2@4750.38,5938.87 ; v2(4745,5994) 4745,5944.25 C121.2@4750.38,5938.87 ; C121.2@4756.21,5933.04 C121.2@4750.38,5938.87 ; R127.2@4827.59,5715.41 v2(4827.59,5743.99)
  Top Layer w14: v2(4540.59,5544.99) 4540.59,5584.26 4540.73,5584.4 C122.2@4541.57,5584.4 U24.5@4601.67,5584.4
  Top Layer w20: U24.5@4601.67,5584.4 U24.5@4601.87,5584.6 ; v2(6018,2362) 6034,2362 6130,2266 C99.1@6130,2257.99 6149.61,2277.6 U18.6@6195.87,2277.6
  Top Layer w30: v1(4103.5,2381.5) 4103.5,2342.58 C47_P.1@4155,2291.09
  Layer 2 w10: v1(4103.5,2381.5) 4105,2383 4105,2399 ; v2(4540.59,5544.99) 4621.01,5544.99 4647,5519 4900.34,5519 ; v2(4549,5300) 4551,5298 4875.34,5298 4900.34,5273 ; v2(4620,4862) 4628.54,4870.54 4708.46,4870.54 4735,4844 ; v2(4827.59,5743.99) 4897.33,5743.99 4900.34,5747
  Layer 2 w20: TP11_P.1@4260,2514 4593,2514 v2(4761,2682) 4775,2696 v2@5684,2696 ; v2(4745,5994) 4825,5994 4900.34,5918.66 4900.34,5747 4900.34,5519 4900.34,5273 v2(4900.34,5155.34) ; v2(4764,3093) 4764,4153 4735,4182 4735,4844 4870,4979 4870,5046 v2@4900,5076
  Layer 2 w30: 4105,2399 4220,2514 TP11_P.1@4260,2514
  Bottom Layer w10: v1(4103.5,2381.5) 4077.93,2381.5 4060,2363.57 4060,2255.59 4086.59,2229 4086.59,2218.9 4113.19,2192.31 D21_P.2@4140,2192.31 ; TP11_P.1@4260,2514 4280,2534 4373.5,2534 C48_P.1@4378.5,2539
  Bottom Layer w20: v2(4761,2682) 4761,3090 v2(4764,3093) ; v2(4900.34,5075.57) v2(4900.34,5155.34) ; v2(5683.5,2695.5) v2@6017,2362
  Bottom Layer w30: R46_P.1@4103.5,2349 C46_P.2@4103.5,2414
+14V: C44_P.1 D1_P.1 D3_P.1 D21_P.1 U8_P.1 U8_P.2 | length 771
  Top Layer w10: v1(4180,2119) 4206.26,2119 4210,2115.26 ; C44_P.1@4222.91,2069 4210,2081.91 4210,2115.26 ; U8_P.2@4260.31,2213.88 U8_P.1@4240.63,2213.88 4234.88,2213.88 4210,2189 4210,2115.26
  Top Layer w30: D1_P.1@4035,2199.53 v1(4035,2244)
  Layer 2 w30: v1(3935,2389) 4035,2289 v1(4035,2244) 4035,2159 4075,2119 v1(4180,2119)
  Bottom Layer w10: D21_P.1@4140,2105.69 4166.69,2105.69 v1(4180,2119)
  Bottom Layer w30: v1(3935,2389) D3_P.1@3935,2419.53
+14V_INV: C43_P.1 C45_P.1 D1_P.2 D20_P.1 R47_P.2 U7_P.23 | length 3070.8
  Top Layer w10: R47_P.2@3274.5,954 C45_P.1@3274.5,884 3274.5,870.5 3296,849 3351,849 3356.47,843.53 U7_P.23@3356.47,818.8
  Top Layer w30: D1_P.2@4035,2328.47 v1(4035,2384)
  Layer 2 w30: v3(3085,1014) 3090,1009 3275,1009 3335,1069 3335,1175.46 3378.54,1219 4054,1219 4124,1289 4364,1289 4450,1375 4450,2037.78 4372.52,2115.26 4283.74,2115.26 4185,2214 4185,2234 v1(4035,2384)
+14V_SW: D2_P.2 D15_P.2 D23_P.2 R1_P.1 T1_P.14 | length 1802.8
  Top Layer w20: T1_P.14@3310,2564 T1_P.14@3325,2579
  Bottom Layer w50: 3210,2564 T1_P.14@3310,2564 3421,2675 4535.26,2675 D15_P.2@4656.26,2554
  Bottom Layer w60: 3350,2559 3355,2559 3376.85,2537.15 D2_P.2@3439.33,2537.15 3416.69,2514.51 3416.69,2409 R1_P.1@3420,2409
